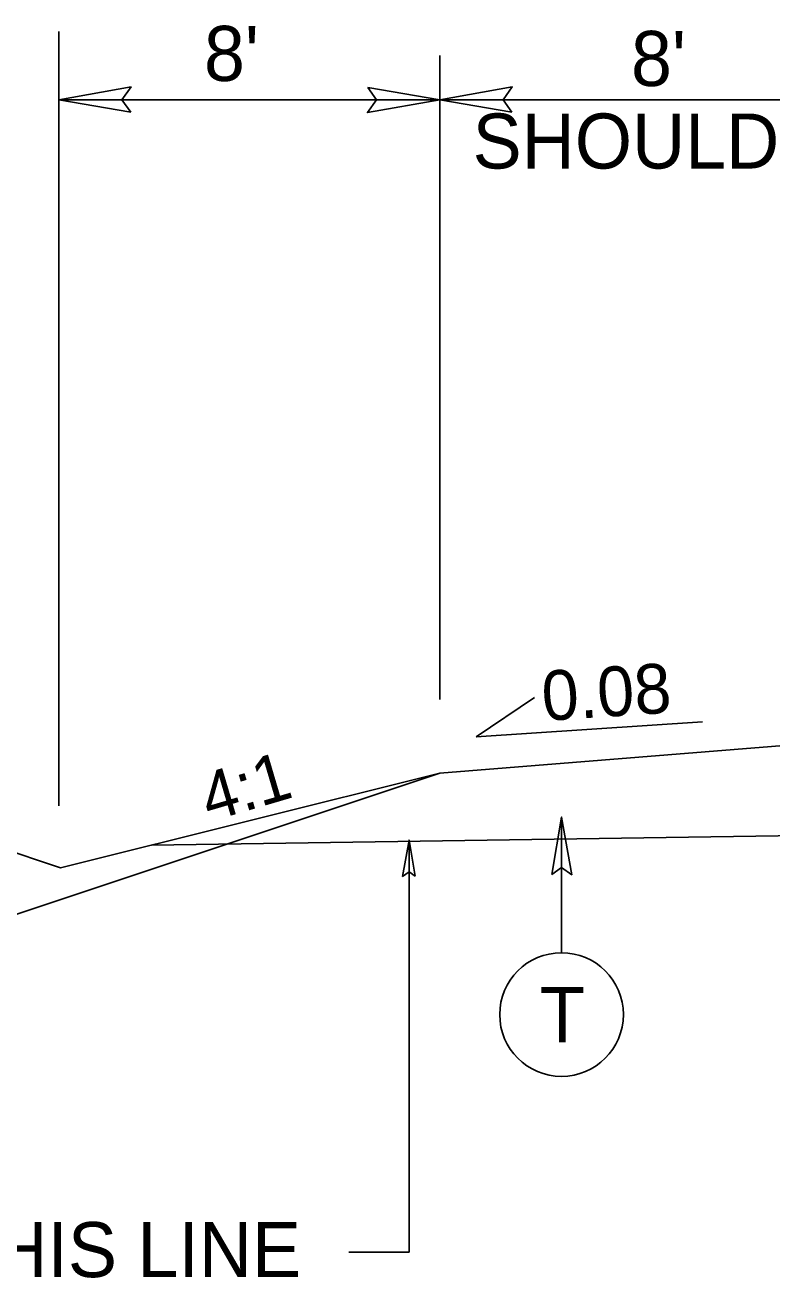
# Model space of a CAD drawing. Extents: x 2176156 to 2177167, y 76401 to 76644.
# Drawn here: x 2176288.55 to 2176304.2, y 76549.85 to 76576.1 of the extents above; entities that cross this region are included whole.
import ezdxf

# ---------------------------------------------------------------- set-up
doc = ezdxf.new("R2010")
doc.units = 0
for name, color, linetype in [('Exist Building', 7, 'Continuous'), ('Exist Roads Curbs', 7, 'Continuous'), ('Exist Roads EOP Other', 7, 'Continuous'), ('Exist Structure Minor Culvert Topo', 7, 'Continuous'), ('Exist Utilities Other Pole CELL', 7, 'Continuous'), ('Old_Level_1', 7, 'Continuous'), ('Old_Level_3', 7, 'Continuous'), ('Prop North Arrow NAD83 for Plan Sheets CELL', 7, 'Continuous')]:
    doc.layers.add(name, color=color, linetype=linetype)

msp = doc.modelspace()

# ---------------------------------------------------------------- linework, layer by layer
at = {"layer": 'Exist Building'}
msp.add_line((2176291.193, 76558.915), (2176312.319, 76559.229), dxfattribs=at)
at = {"layer": 'Exist Roads EOP Other'}
for p, q in [((2176289.287, 76558.438), (2176279.287, 76561.772)), ((2176307.239, 76561.226), (2176297.239, 76560.426)), ((2176278.629, 76554.223), (2176297.239, 76560.426)), ((2176289.287, 76558.438), (2176297.239, 76560.426))]:
    msp.add_line(p, q, dxfattribs=at)
at = {"layer": 'Exist Utilities Other Pole CELL'}
for q in [(2176299.223, 76562.007), (2176302.744, 76561.501)]:
    msp.add_line((2176297.998, 76561.187), q, dxfattribs=at)
at = {"layer": 'Old_Level_1'}
for points in [[(2176290.761, 76574.275), (2176289.252, 76574.535), (2176290.77, 76574.803), (2176290.577, 76574.535)], [(2176295.729, 76574.795), (2176297.239, 76574.535), (2176295.721, 76574.267), (2176295.914, 76574.535)], [(2176298.749, 76574.275), (2176297.239, 76574.535), (2176298.757, 76574.803), (2176298.564, 76574.535)], [(2176296.724, 76558.266), (2176296.594, 76559.02), (2176296.459, 76558.261), (2176296.594, 76558.358)]]:
    msp.add_lwpolyline(points, close=True, dxfattribs=at)
at = {"layer": 'Old_Level_3'}
for p, q in [((2176289.252, 76559.738), (2176289.252, 76575.968)), ((2176297.239, 76561.964), (2176297.239, 76575.463)), ((2176297.239, 76574.535), (2176289.252, 76574.535)), ((2176307.239, 76574.535), (2176297.239, 76574.535)), ((2176296.594, 76559.02), (2176296.594, 76550.385)), ((2176295.333, 76550.385), (2176296.594, 76550.385))]:
    msp.add_line(p, q, dxfattribs=at)
at = {"layer": 'Prop North Arrow NAD83 for Plan Sheets CELL'}
msp.add_line((2176299.79, 76556.66), (2176299.79, 76559.502), dxfattribs=at)
msp.add_lwpolyline([(2176299.584, 76558.302), (2176299.79, 76559.502), (2176300.004, 76558.296), (2176299.79, 76558.449)], close=True, dxfattribs=at)
msp.add_circle((2176299.79, 76555.364), 1.296, dxfattribs=at)

# ---------------------------------------------------------------- texts
at = {"layer": 'Exist Roads Curbs'}
msp.add_text('4:1', height=1.0064, rotation=16.4649, dxfattribs=at).set_placement((2176292.408, 76559.399))
at = {"layer": 'Exist Structure Minor Culvert Topo'}
for s, height, p in [("8'", 1.1533, (2176292.296, 76574.93)), ("8'", 1.1533, (2176301.245, 76574.824)), ('SHOULDER', 1.1533, (2176297.925, 76573.094)), ('GRADE TO THIS LINE', 1.15334, (2176278.477, 76549.862))]:
    msp.add_text(s, height=height, dxfattribs=at).set_placement(p)
at = {"layer": 'Exist Utilities Other Pole CELL'}
msp.add_text('0.08', height=1.0429, rotation=3.7801, dxfattribs=at).set_placement((2176299.408, 76561.517))
at = {"layer": 'Prop North Arrow NAD83 for Plan Sheets CELL'}
msp.add_text('T', height=1.16, rotation=359.9997, dxfattribs=at).set_placement((2176299.333, 76554.784))

doc.saveas('drawing.dxf')
